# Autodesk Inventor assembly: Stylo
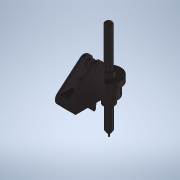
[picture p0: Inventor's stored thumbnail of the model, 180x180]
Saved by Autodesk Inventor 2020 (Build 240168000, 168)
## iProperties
Created: 2017-09
Part Number: Stylo
Document SubType Name: Assembly
Designer: bruno
Mass: 50.3616 g
Surface Area: 292.733 cm^2
Volume: 51.3487 cm^3
Density: 0.980777 g/cm^3
Sending System: SolidWorks 2016
Last Author: Prof
Last Saved: 2018-10-31
Author: bruno
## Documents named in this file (3)
- C:\Users\bruno\Documents\Systèmes\Mallette Bras robotisé (273265)\Dossier ressources\Maquette Dobot SW2016\Stylo.iam
- C:\Users\bruno\Documents\Systèmes\Mallette Bras robotisé (273265)\Dossier ressources\Maquette Dobot SW2016\support stylo^robot.iam
- C:\Users\bruno\Documents\Systèmes\Mallette Bras robotisé (273265)\Dossier ressources\Maquette Dobot SW2016\poignet^robot.iam
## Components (2 placed, 2 different names)
1. support stylo:1 [sub-assembly]
2. poignet^robot:1 [sub-assembly]
